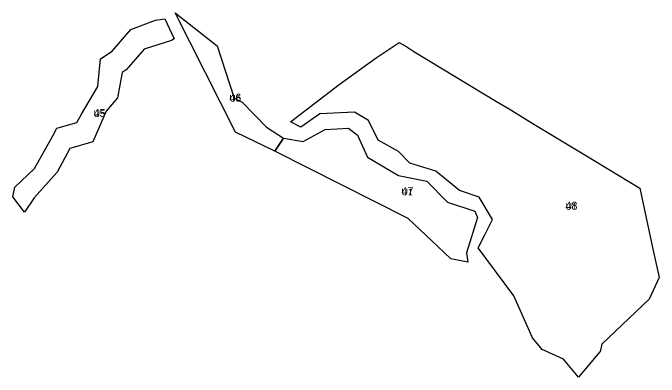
# Model space of a CAD drawing. Extents: x -521229 to -518220, y -1182332 to -1179899.
# Drawn here: x -520103.9 to -519619.9, y -1180241.3 to -1179968.2 of the extents above; entities that cross this region are included whole.
import ezdxf

# ---------------------------------------------------------------- set-up
doc = ezdxf.new("R2010")
doc.units = 0
doc.layers.add('96140023', color=7, linetype='Continuous')
doc.layers.add('ID_VPO', color=7, linetype='Continuous')

msp = doc.modelspace()

# ---------------------------------------------------------------- linework, layer by layer
at = {"layer": '96140023'}
for points in [[(-519907.69, -1180071.91), (-519937.13, -1180057.7), (-519982.32, -1179968.2), (-519950.91, -1179992.96), (-519938.11, -1180032.03), (-519932.27, -1180035.16), (-519914.01, -1180053.95), (-519901.2, -1180062.26)], [(-520088, -1180107), (-520095.27, -1180117.7), (-520103.91, -1180106.03), (-520102.56, -1180098.8), (-520087.72, -1180084.77), (-520074.1, -1180060.33), (-520070.98, -1180054.76), (-520056.11, -1180050.48), (-520052.55, -1180044.22), (-520040.38, -1180023.43), (-520040.02, -1180020.63), (-520038.42, -1180002.72), (-520029.65, -1179996.94), (-520015.68, -1179980.65), (-519997.12, -1179973.52), (-519990.22, -1179972.72), (-519983.06, -1179987.64), (-519985.05, -1179988.8), (-520005.55, -1179995.44), (-520018.98, -1180010.78), (-520022.08, -1180012.82), (-520025.61, -1180031.84), (-520033.98, -1180041.98), (-520044.01, -1180064.98), (-520061.4, -1180069.98), (-520070.87, -1180087.57)], [(-519619.93, -1180166.69), (-519627.35, -1180182.92), (-519662.7, -1180216.65), (-519664.04, -1180222.22), (-519667.04, -1180225.61), (-519680.38, -1180241.32), (-519691.45, -1180227.98), (-519707.49, -1180220.58), (-519714.78, -1180211.92), (-519728.69, -1180180.4), (-519755.54, -1180144.42), (-519750.38, -1180134.69), (-519744.71, -1180123.1), (-519754.65, -1180106.41), (-519769.42, -1180101.42), (-519787.03, -1180086.82), (-519806.74, -1180080.96), (-519814.99, -1180072.13), (-519830.39, -1180063.53), (-519837.62, -1180048.87), (-519847.98, -1180042.57), (-519874.13, -1180043.77), (-519888.14, -1180053.8), (-519896.06, -1180049.84), (-519859.45, -1180022.01), (-519831.9, -1180001.88), (-519814.62, -1179990.28), (-519808.96, -1179993.71), (-519803.62, -1179997.22), (-519741.66, -1180034.52), (-519732.23, -1180040.25), (-519713.64, -1180051.54), (-519675.47, -1180074.7), (-519634.46, -1180099.59), (-519624.93, -1180144.25)], [(-519807.85, -1180122.32), (-519907.69, -1180071.91), (-519901.2, -1180062.26), (-519886.44, -1180064.71), (-519870.04, -1180055.63), (-519852.63, -1180054.73), (-519845.87, -1180059.96), (-519838.3, -1180076.34), (-519815.23, -1180090.06), (-519793.98, -1180094.42), (-519778.3, -1180110.21), (-519757.91, -1180116.91), (-519755.81, -1180121.7), (-519764.13, -1180148.17), (-519763.15, -1180155.18), (-519775.91, -1180152.74), (-519790.24, -1180139.09)]]:
    msp.add_lwpolyline(points, close=True, dxfattribs=at)

# ---------------------------------------------------------------- texts
for s, rotation, p in [('U5', 360, (-519941.76, -1180034.71)), ('U5', 0, (-520043.48, -1180046.26)), ('U1', 360, (-519812.88, -1180104.96)), ('U1', 360, (-519690.03, -1180115.8))]:
    msp.add_text(s, height=5, rotation=rotation, dxfattribs=at).set_placement(p)
at = {"layer": 'ID_VPO'}
msp.add_text('46', height=6, dxfattribs=at).set_placement((-519941.76, -1180034.71))
for s, rotation, p in [('45', 0, (-520043.48, -1180046.26)), ('47', 360, (-519812.88, -1180104.96)), ('48', 360, (-519690.03, -1180115.8))]:
    msp.add_text(s, height=6, rotation=rotation, dxfattribs=at).set_placement(p)

doc.saveas('drawing.dxf')
